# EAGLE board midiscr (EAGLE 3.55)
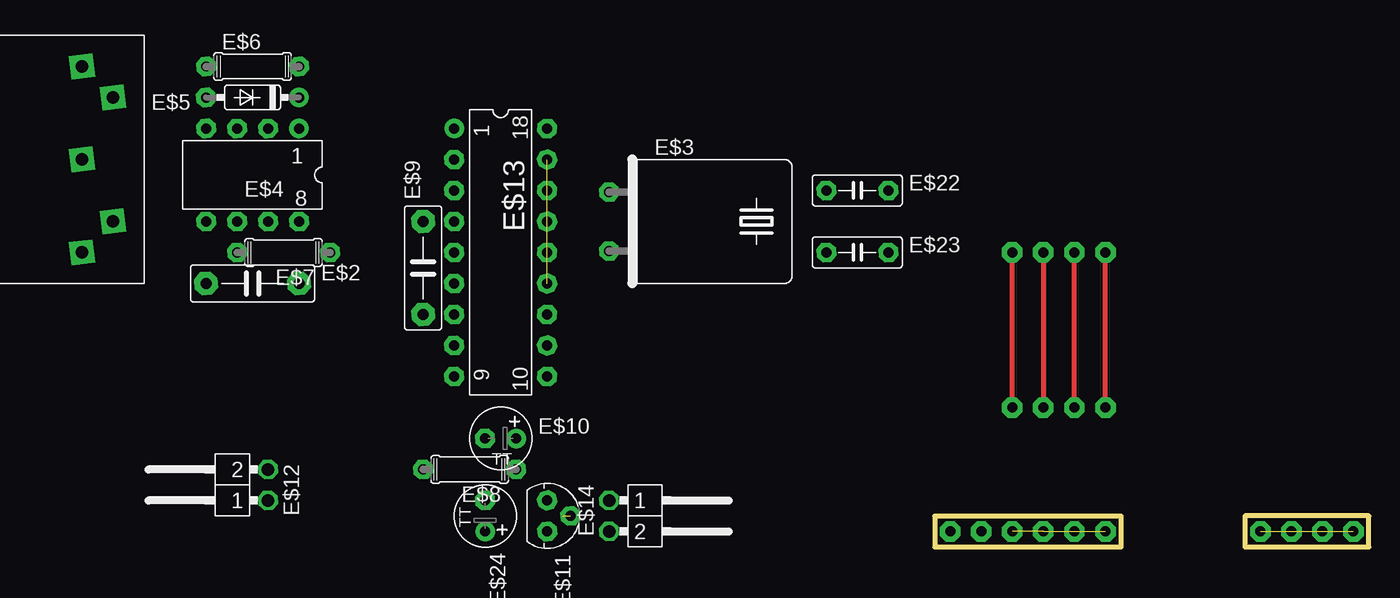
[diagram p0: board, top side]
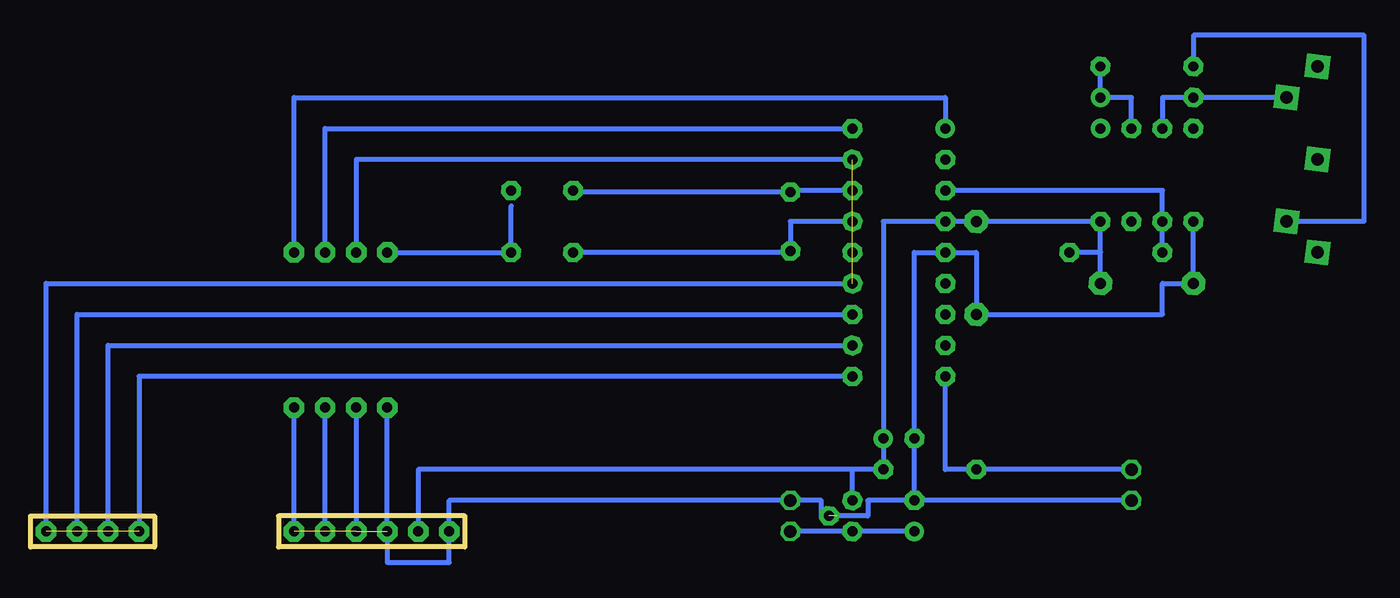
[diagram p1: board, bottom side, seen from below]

Size 35.56 x 2.54 mm. Coordinates in mm from the lower left corner, seen from the top.
Outline: 0,2.54 0,0 15.24,0 15.24,2.54 0,2.54
Outline: 25.4,2.54 25.4,0 35.56,0 35.56,2.54 25.4,2.54
Copper layers used: Top, Bottom

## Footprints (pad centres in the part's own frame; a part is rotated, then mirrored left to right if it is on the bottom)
_PCB = drill 1.016 pad 1.93 square:  -7.62,10.16;  -5.08,10.16;  0,10.16;  2.54,10.16;  -2.54,0;  -7.62,-2.54;  -10.16,0;  2.54,-2.54;  5.08,0
,5B3 = drill 0.914 pad 1.905 octagon:  -3.81,0;  3.81,0
49U-H = drill 0.813 pad 1.6 octagon:  -2.413,-5.08;  2.413,-5.08
L08 = drill 0.813 pad 1.6 round:  -3.81,-3.81 | drill 0.813 pad 1.6 octagon:  -1.27,-3.81;  1.27,-3.81;  3.81,-3.81;  3.81,3.81;  1.27,3.81;  -1.27,3.81;  -3.81,3.81
35-7 = drill 0.813 pad 1.6 round:  -3.81,0 | drill 0.813 pad 1.6 octagon:  3.81,0
07/7 = drill 0.813 pad 1.6 octagon:  -3.81,0;  3.81,0
2D5 = drill 0.813 pad 1.6 octagon:  -1.27,0 | drill 0.813 pad 1.6 round:  1.27,0
LXX = drill 0.813 pad 1.6 octagon:  -1.27,0;  0,1.905;  1.27,0
02-1W = drill 1.016 pad 1.6 octagon:  -8.89,-3.81;  -11.43,-3.81
L18 = drill 0.813 pad 1.6 round:  -10.16,-3.81 | drill 0.813 pad 1.6 octagon:  -7.62,-3.81;  -5.08,-3.81;  -2.54,-3.81;  0,-3.81;  2.54,-3.81;  5.08,-3.81;  7.62,-3.81;  10.16,-3.81;  10.16,3.81;  7.62,3.81;  5.08,3.81;  2.54,3.81;  0,3.81;  -2.54,3.81;  -5.08,3.81;  -7.62,3.81;  -10.16,3.81
B2,5 = drill 0.813 pad 1.6 octagon:  -2.54,0;  2.54,0

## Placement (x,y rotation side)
E$1  [_PCB]  not placed on the board
E$2  [,5B3]  -55.88,21.59 0 top  (outside the outline)
E$3  [49U-H]  -21.59,26.67 270 top  (outside the outline)
E$4  [L08]  -55.88,30.48 180 top  (outside the outline)
E$5  [35-7]  -55.88,36.83 180 top  (outside the outline)
E$6  [07/7]  -55.88,39.37 0 top  (outside the outline)
E$7  [07/7]  -53.34,24.13 180 top  (outside the outline)
E$8  [07/7]  -38.1,6.35 180 top  (outside the outline)
E$9  [,5B3]  -41.91,22.86 90 top  (outside the outline)
E$10  [2D5]  -35.56,8.89 0 top  (outside the outline)
E$11  [LXX]  -31.75,2.54 270 top  (outside the outline)
E$12  [02-1W]  -58.42,15.24 90 top  (outside the outline)
E$13  [L18]  -35.56,24.13 270 top  (outside the outline)
E$14  [02-1W]  -22.86,-7.62 270 top  (outside the outline)
E$22  [B2,5]  not placed on the board
E$23  [B2,5]  -6.35,24.13 0 top  (outside the outline)
E$24  [2D5]  -36.83,2.54 270 top  (outside the outline)

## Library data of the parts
E$1 = con-din
E$2 E$9 E$22 E$23 = cap
E$3 = quartz
E$4 = optocpl
E$5 = diode
E$6-E$8 = r
E$10 E$24 = cap-tant
E$11 = v-reg
E$12 E$14 = CON-LSTB
E$13 = pic

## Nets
S$1: E$1. E$6.
S$2: E$4. E$7. E$13.
S$3: E$11. E$14. E$24.
S$4: E$3. E$13. E$22.
S$5: E$3. E$13. E$23.
S$10: E$2. E$4. E$7. E$8. E$9. E$10. E$11. E$13.
S$11: E$2. E$4. E$9. E$10. E$11. E$12. E$13. E$14. E$23. E$24.
S$17: E$1. E$4. E$5.
S$19: E$4. E$5. E$6.
S$21: E$8. E$12. E$13.

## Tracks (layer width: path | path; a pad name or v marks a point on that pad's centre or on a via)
S$1
  Bottom 0.406: -67.31,26.67 -73.66,26.67 -73.66,41.91 -59.69,41.91 -59.69,39.37
S$2
  Bottom 0.406: E$7. -57.15,26.67 -57.15,29.21 -39.37,29.21
S$3
  Bottom 0.406: E$24. E$11. -26.67,1.27
S$4
  Bottom 0.406: -31.75,29.21 -26.67,29.21 -26.67,29.08 -8.89,29.08 -8.89,29.21
S$5
  Bottom 0.406: -31.75,26.67 -26.67,26.67 E$3. -26.67,24.13 -8.89,24.13
S$10  (via drill 0.81 pad 1.68)
  Bottom 0.406: -52.07,24.13 E$4. E$9. -39.37,26.67 -34.29,26.67 E$10. -34.29,6.35 -31.75,6.35 | -52.07,24.13 -49.53,24.13 | E$2. -52.07,24.13 | v3.81,1.27 3.81,6.35 -31.75,6.35 | -31.75,3.81 -31.75,6.35
S$11  (via drill 0.81 pad 1.68)  (8 unrouted)
  Top 0.406: v6.35,11.43 v6.35,24.13 | v8.89,24.13 v8.89,11.43 | v11.43,11.43 v11.43,24.13 | v13.97,11.43 v13.97,24.13
  Bottom 0.406: v6.35,11.43 v6.35,1.27 6.35,-1.27 1.27,-1.27 v1.27,1.27 1.27,3.81 E$14. -29.21,3.81 -29.21,2.54 -29.84,2.54 | v8.89,11.43 v8.89,1.27 | v11.43,1.27 v11.43,11.43 | v13.97,1.27 v13.97,11.43 | v26.67,1.27 26.67,13.97 -31.75,13.97 | -31.75,16.51 29.21,16.51 v29.21,1.27 | v31.75,1.27 31.75,19.05 -31.75,19.05 | -31.75,21.59 34.29,21.59 v34.29,1.27 | -31.75,31.75 8.89,31.75 v8.89,24.13 | v11.43,24.13 11.43,34.29 E$13. | -39.37,34.29 -39.37,36.83 13.97,36.83 v13.97,24.13 | -3.81,27.94 E$23. v6.35,24.13 | -59.69,26.67 -59.69,21.59 -57.15,21.59 -57.15,19.05 -41.91,19.05 -41.91,24.13 -39.37,24.13 -36.83,24.13 -36.83,8.89 -36.83,3.81 | E$12. -36.83,3.81 | -36.83,3.81 -33.02,3.81 -33.02,2.54 -30.48,2.54
S$17
  Bottom 0.406: -57.15,34.29 -57.15,36.83 E$5. -67.31,36.83
S$19
  Bottom 0.406: E$6. -52.07,36.83 -54.61,36.83 -54.61,34.29
S$21
  Bottom 0.406: -39.37,13.97 -39.37,6.35 E$8. -54.61,6.35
